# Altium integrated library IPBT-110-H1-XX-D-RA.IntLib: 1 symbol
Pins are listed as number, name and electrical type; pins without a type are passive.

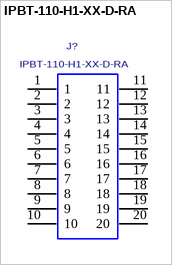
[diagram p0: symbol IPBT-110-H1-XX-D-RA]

## IPBT-110-H1-XX-D-RA
designator J?
Terminal Assembly, Double Row, Right Angle, Thru-Hole, 0.100" x 0.100" Pitch.; MANUFACTURER: SAMTEC
footprint IPBT-110-H1-XX-D-RA
pins: 1, 2, 3, 4, 5, 6, 7, 8, 9, 10, 11, 12, 13, 14, 15, 16, 17, 18, 19, 20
